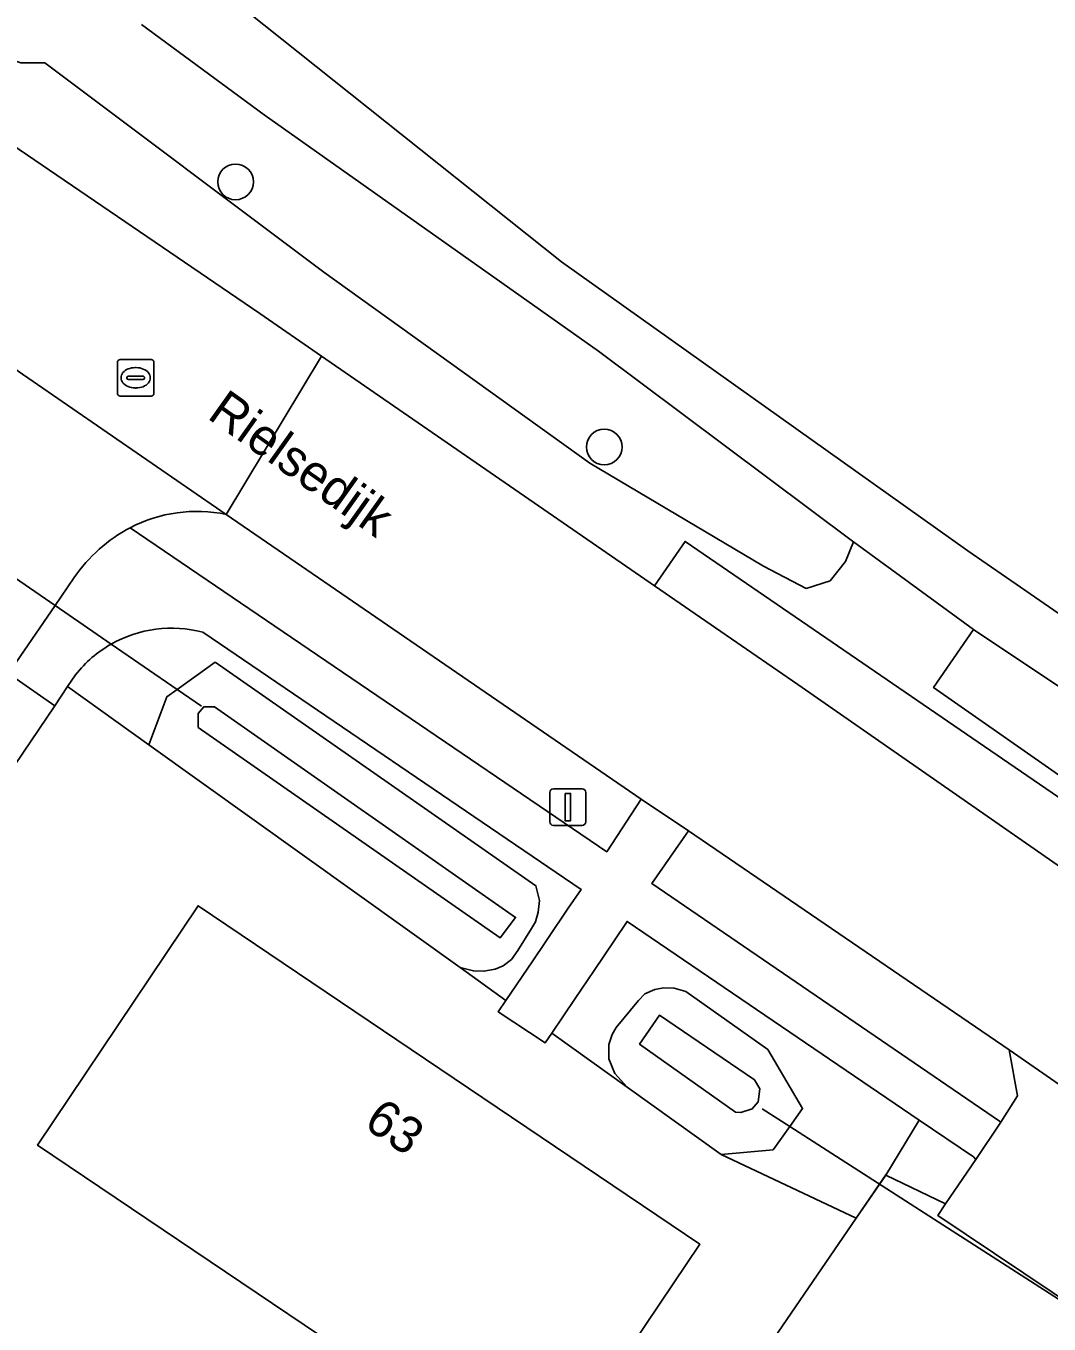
# Model space of a CAD drawing. Extents: x 163859 to 164644, y 379566 to 382155.
# Drawn here: x 164197.07 to 164225.13, y 381831.56 to 381867.17 of the extents above; entities that cross this region are included whole.
import ezdxf

# ---------------------------------------------------------------- set-up
doc = ezdxf.new("R2010")
doc.units = 0
for name, color, linetype in [('IMGEO_Boom', 7, 'Continuous'), ('IMGEO_Duiker', 7, 'Continuous'), ('IMGEO_Erf', 7, 'Continuous'), ('IMGEO_Grasland_agrarisch', 7, 'Continuous'), ('IMGEO_Grasland_overig', 7, 'Continuous'), ('IMGEO_Groenvoorziening', 7, 'Continuous'), ('IMGEO_Lichtmast', 7, 'Continuous'), ('IMGEO_Muur', 7, 'Continuous'), ('IMGEO_Oever', 7, 'Continuous'), ('IMGEO_Openbare_ruimte_label', 7, 'Continuous'), ('IMGEO_Pand', 7, 'Continuous'), ('IMGEO_Pand_nummerreeks', 7, 'Continuous'), ('IMGEO_Parkeervlak_halfverhard', 7, 'Continuous'), ('IMGEO_Rijbaan_lokaal_gesloten', 7, 'Continuous'), ('IMGEO_Rijbaan_lokaal_open', 7, 'Continuous'), ('IMGEO_Rioolput', 7, 'Continuous'), ('IMGEO_Sloot', 7, 'Continuous'), ('IMGEO_Voetpad_halfverhard', 7, 'Continuous'), ('IMGEO_Voetpad_open', 7, 'Continuous'), ('IMGEO_Waterloop', 7, 'Continuous')]:
    doc.layers.add(name, color=color, linetype=linetype)

msp = doc.modelspace()

# ---------------------------------------------------------------- linework, layer by layer
at = {"layer": 'IMGEO_Boom'}
for centre in [(164202.821, 381862.893), (164212.934, 381855.62)]:
    msp.add_circle(centre, 0.489, dxfattribs=at)
at = {"layer": 'IMGEO_Duiker'}
for points in [[(164190.042, 381856.658), (164190.846, 381856.104), (164192.323, 381855.089), (164194.104, 381853.864), (164197.871, 381851.272), (164199.409, 381850.214), (164201.216, 381848.971), (164201.883, 381848.512)], [(164217.268, 381837.469), (164218.022, 381836.985), (164233.632, 381826.955)]]:
    msp.add_lwpolyline(points, dxfattribs=at)
at = {"layer": 'IMGEO_Erf'}
for points in [[(164235.043, 381794.138), (164205.955, 381814.209), (164212.364, 381823.54), (164216.274, 381829.253), (164219.843, 381834.466), (164216.141, 381836.213), (164213.566, 381838.056), (164211.492, 381839.541), (164211.311, 381839.272), (164210.023, 381840.13), (164210.234, 381840.441), (164208.977, 381841.341), (164200.437, 381847.454), (164198.212, 381849.047), (164197.859, 381848.521), (164188.424, 381834.578), (164188.626, 381834.431), (164188.179, 381833.768), (164185.088, 381829.228), (164165.885, 381800.687)], [(164287.783, 381790.232), (164256.006, 381812.389), (164255.882, 381812.656), (164254.893, 381811.01), (164254.142, 381811.525), (164232.273, 381826.526), (164232.842, 381827.338), (164225.998, 381831.919), (164222.08, 381834.543), (164222.298, 381834.862), (164220.66, 381835.65), (164219.843, 381834.466), (164216.274, 381829.253), (164224.066, 381823.939), (164225.891, 381826.571), (164230.279, 381823.603), (164230.417, 381823.852)]]:
    msp.add_lwpolyline(points, dxfattribs=at)
msp.add_lwpolyline([(164197.39, 381836.467), (164201.794, 381843.035), (164208.819, 381838.297), (164215.56, 381833.752), (164211.149, 381827.193)], close=True, dxfattribs=at)
at = {"layer": 'IMGEO_Grasland_agrarisch'}
msp.add_lwpolyline([(164303.655, 381951.333), (164266.944, 381922.737), (164277.667, 381908.3), (164278.876, 381906.816), (164278.809, 381906.762), (164279.852, 381905.358), (164303.691, 381871.549), (164284.619, 381860.24), (164259.755, 381889.448), (164267.387, 381895.767), (164258.029, 381908.469), (164254.791, 381905.941), (164252.396, 381909.265), (164208.654, 381876.058), (164201.663, 381868.745), (164211.763, 381860.7), (164222.906, 381852.769), (164256.457, 381829.627), (164286.005, 381809.753), (164322.428, 381783.408), (164335.006, 381775.051), (164338.747, 381777.229), (164392.726, 381806.597)], dxfattribs=at)
at = {"layer": 'IMGEO_Grasland_overig'}
for points in [[(164286.005, 381809.753), (164256.457, 381829.627), (164222.906, 381852.769), (164211.763, 381860.7), (164201.663, 381868.745)], [(164200.241, 381867.209), (164203.607, 381864.729), (164212.773, 381858.254), (164219.743, 381853.042), (164219.769, 381853.023), (164223.061, 381850.617), (164244.45, 381836.352), (164263.512, 381823.639), (164264.597, 381822.915)], [(164202.265, 381849.716), (164211.061, 381843.586), (164211.155, 381843.184), (164211.125, 381842.859), (164211.052, 381842.593), (164210.941, 381842.409), (164210.564, 381841.812), (164210.386, 381841.558), (164210.157, 381841.388), (164209.943, 381841.299), (164209.632, 381841.24), (164209.344, 381841.247), (164208.977, 381841.341), (164210.234, 381840.441), (164210.971, 381841.528), (164211.31, 381842.028), (164211.367, 381842.112), (164211.947, 381842.968), (164212.298, 381843.486), (164201.922, 381850.538)], [(164198.432, 381849.375), (164198.212, 381849.047), (164200.437, 381847.454), (164200.931, 381848.768), (164201.216, 381848.971), (164202.265, 381849.716)]]:
    msp.add_lwpolyline(points, dxfattribs=at)
for centre, radius, start, end in [((164201.063, 381847.292), 3.358, 75.1807, 119.5125), ((164201.064, 381847.299), 3.352, 119.5802, 141.7285)]:
    msp.add_arc(centre, radius, start, end, dxfattribs=at)
at = {"layer": 'IMGEO_Groenvoorziening'}
for points in [[(164261.825, 381821.183), (164221.968, 381849.023), (164223.061, 381850.617), (164219.769, 381853.023), (164219.553, 381852.482), (164219.129, 381851.953), (164218.468, 381851.741), (164217.304, 381852.35), (164212.541, 381855.181), (164205.239, 381860.42), (164197.592, 381866.161), (164196.931, 381866.161), (164195.529, 381866.611), (164195.052, 381867.457), (164195.268, 381868.391), (164195.29, 381868.489), (164195.394, 381868.583), (164194.945, 381868.909), (164183.031, 381877.576), (164180.902, 381879.968), (164176.8, 381882.795)], [(164175.458, 381878.387), (164203.483, 381859.285), (164205.181, 381858.114), (164214.31, 381851.815), (164215.15, 381853.032), (164227.892, 381844.304), (164227.341, 381843.488), (164229.978, 381841.659), (164230.539, 381842.463), (164236.331, 381838.448), (164235.41, 381837.168), (164242.387, 381832.326), (164242.758, 381832.059), (164272.361, 381810.742), (164289.667, 381798.436), (164312.339, 381782.446)], [(164199.933, 381853.407), (164213.001, 381844.519), (164213.948, 381845.959), (164202.562, 381853.773)]]:
    msp.add_lwpolyline(points, dxfattribs=at)
for points in [[(164215.248, 381845.088), (164214.237, 381843.648), (164223.774, 381837.13), (164223.813, 381837.103), (164224.271, 381837.825), (164224.041, 381839.088)], [(164221.574, 381837.159), (164213.561, 381842.608), (164213.204, 381842.078), (164212.655, 381841.264), (164212.135, 381840.494), (164211.492, 381839.541), (164213.566, 381838.056), (164213.223, 381838.437), (164213.061, 381838.836), (164213.061, 381839.228), (164213.15, 381839.509), (164213.258, 381839.698), (164213.869, 381840.436), (164214.044, 381840.618), (164214.325, 381840.736), (164214.561, 381840.788), (164214.849, 381840.78), (164215.169, 381840.688), (164217.418, 381839.098), (164218.372, 381837.475), (164218.022, 381836.985), (164217.566, 381836.344), (164216.141, 381836.213), (164219.843, 381834.466), (164220.66, 381835.65)], [(164223.128, 381836.076), (164223.059, 381836.149), (164221.574, 381837.159), (164220.66, 381835.65), (164222.298, 381834.862)]]:
    msp.add_lwpolyline(points, close=True, dxfattribs=at)
msp.add_arc((164201.76, 381849.906), 3.949, 78.2887, 117.5624, dxfattribs=at)
at = {"layer": 'IMGEO_Lichtmast'}
for p, q in [((164211.438, 381845.342), (164211.438, 381846.142)), ((164211.438, 381846.142), (164211.438, 381845.342)), ((164211.538, 381846.242), (164212.328, 381846.242)), ((164212.328, 381846.242), (164211.538, 381846.242)), ((164212.428, 381846.142), (164212.428, 381845.342)), ((164212.428, 381845.342), (164212.428, 381846.142)), ((164212.328, 381845.242), (164211.538, 381845.242)), ((164211.538, 381845.242), (164212.328, 381845.242))]:
    msp.add_line(p, q, dxfattribs=at)
msp.add_lwpolyline([(164211.858, 381846.117), (164212.008, 381846.117), (164212.008, 381845.367), (164211.858, 381845.367), (164211.858, 381846.117)], dxfattribs=at)
for centre, start, end in [((164211.538, 381846.142), 90, 180), ((164211.538, 381846.142), 90, 180), ((164212.328, 381846.142), 0, 90), ((164212.328, 381846.142), 360, 90), ((164211.538, 381845.342), 180, 270), ((164211.538, 381845.342), 180, 270), ((164212.328, 381845.342), 270, 0), ((164212.328, 381845.342), 270, 0)]:
    msp.add_arc(centre, 0.1, start, end, dxfattribs=at)
at = {"layer": 'IMGEO_Muur'}
for points in [[(164219.843, 381834.466), (164220.477, 381835.391)], [(164220.477, 381835.391), (164220.655, 381835.651)], [(164216.274, 381829.253), (164219.843, 381834.466)]]:
    msp.add_lwpolyline(points, dxfattribs=at)
at = {"layer": 'IMGEO_Oever'}
for points in [[(164202.265, 381849.716), (164201.216, 381848.971), (164200.931, 381848.768), (164200.437, 381847.454), (164208.977, 381841.341), (164209.344, 381841.247), (164209.632, 381841.24), (164209.943, 381841.299), (164210.157, 381841.388), (164210.386, 381841.558), (164210.564, 381841.812), (164210.941, 381842.409), (164211.052, 381842.593), (164211.125, 381842.859), (164211.155, 381843.184), (164211.061, 381843.586)], [(164201.946, 381848.491), (164202.241, 381848.491), (164210.501, 381842.717), (164210.075, 381842.154), (164201.798, 381847.929), (164201.798, 381848.313)], [(164218.372, 381837.475), (164217.418, 381839.098), (164215.169, 381840.688), (164214.849, 381840.78), (164214.561, 381840.788), (164214.325, 381840.736), (164214.044, 381840.618), (164213.869, 381840.436), (164213.258, 381839.698), (164213.15, 381839.509), (164213.061, 381839.228), (164213.061, 381838.836), (164213.223, 381838.437), (164213.566, 381838.056), (164216.141, 381836.213), (164217.566, 381836.344), (164218.022, 381836.985)], [(164216.993, 381837.465), (164216.683, 381837.362), (164216.535, 381837.376), (164213.901, 381839.242), (164214.453, 381840.037), (164217.052, 381838.263), (164217.2, 381838.012), (164217.156, 381837.657)]]:
    msp.add_lwpolyline(points, close=True, dxfattribs=at)
at = {"layer": 'IMGEO_Pand'}
msp.add_lwpolyline([(164201.794, 381843.035), (164197.39, 381836.467), (164211.149, 381827.193), (164215.56, 381833.752), (164208.819, 381838.297)], close=True, dxfattribs=at)
at = {"layer": 'IMGEO_Parkeervlak_halfverhard'}
msp.add_lwpolyline([(164215.15, 381853.032), (164214.31, 381851.815), (164218.242, 381849.102), (164233.939, 381838.189), (164234.184, 381838.019), (164235.41, 381837.168), (164236.331, 381838.448), (164230.539, 381842.463), (164229.978, 381841.659), (164227.341, 381843.488), (164227.892, 381844.304)], close=True, dxfattribs=at)
at = {"layer": 'IMGEO_Rijbaan_lokaal_gesloten'}
for points in [[(164184.975, 381865.791), (164193.85, 381859.772), (164202.562, 381853.773), (164205.181, 381858.114), (164203.483, 381859.285), (164175.458, 381878.387), (164175.446, 381878.395), (164166.649, 381884.443), (164166.499, 381884.544), (164143.584, 381899.974), (164141.791, 381898.302), (164187.087, 381867.645)], [(164218.242, 381849.102), (164214.31, 381851.815), (164205.181, 381858.114), (164202.562, 381853.773), (164213.948, 381845.959), (164215.248, 381845.088), (164224.041, 381839.088), (164229.404, 381835.36), (164230.42, 381834.663), (164231.119, 381834.18), (164233.939, 381838.189)]]:
    msp.add_lwpolyline(points, close=True, dxfattribs=at)
at = {"layer": 'IMGEO_Rijbaan_lokaal_open'}
for points in [[(164202.562, 381853.773), (164193.85, 381859.772)], [(164183.294, 381829.671), (164187.087, 381835.261), (164196.592, 381849.406), (164197.871, 381851.272), (164198.396, 381852.037)]]:
    msp.add_lwpolyline(points, dxfattribs=at)
msp.add_lwpolyline([(164224.041, 381839.088), (164224.271, 381837.825), (164223.813, 381837.103), (164223.128, 381836.076), (164222.298, 381834.862), (164222.08, 381834.543), (164225.998, 381831.919), (164227.089, 381833.448), (164227.793, 381834.436), (164227.67, 381834.52), (164228.079, 381835.092), (164229.404, 381835.36)], close=True, dxfattribs=at)
for centre, radius, start, end in [((164201.76, 381849.906), 3.949, 78.2887, 117.5624), ((164201.849, 381849.71), 4.164, 117.3979, 146.0263)]:
    msp.add_arc(centre, radius, start, end, dxfattribs=at)
at = {"layer": 'IMGEO_Rioolput'}
for p, q in [((164199.579, 381857.093), (164199.579, 381857.945)), ((164199.654, 381858.019), (164200.506, 381858.019)), ((164200.067, 381857.799), (164200.092, 381857.799)), ((164200.58, 381857.945), (164200.58, 381857.093)), ((164199.838, 381857.513), (164199.838, 381857.525)), ((164200.276, 381857.476), (164199.878, 381857.476)), ((164199.881, 381857.562), (164200.279, 381857.562)), ((164200.322, 381857.525), (164200.322, 381857.513)), ((164200.09, 381857.239), (164200.065, 381857.239)), ((164200.506, 381857.019), (164199.654, 381857.019))]:
    msp.add_line(p, q, dxfattribs=at)
for points in [[(164199.579, 381857.093), (164199.579, 381857.945)], [(164199.654, 381858.019), (164200.506, 381858.019)], [(164200.58, 381857.945), (164200.58, 381857.093)], [(164200.506, 381857.019), (164199.654, 381857.019)]]:
    msp.add_lwpolyline(points, dxfattribs=at)
for centre, radius, start, end in [((164199.656, 381857.943), 0.0765, 91.552, 178.448), ((164199.656, 381857.943), 0.0765, 91.552, 178.448), ((164200.504, 381857.943), 0.0765, 1.552, 88.448), ((164200.504, 381857.943), 0.0765, 1.552, 88.448), ((164199.878, 381857.522), 0.0403, 85.8775, 175.7526), ((164199.875, 381857.512), 0.0366, 178.938, 274.7102), ((164200.279, 381857.519), 0.043, 264.8664, 352.4533), ((164200.283, 381857.524), 0.0386, 1.7309, 96.639), ((164199.656, 381857.095), 0.0765, 181.552, 268.448), ((164199.656, 381857.095), 0.0765, 181.552, 268.448), ((164200.504, 381857.095), 0.0765, 271.552, 358.448), ((164200.504, 381857.095), 0.0765, 271.552, 358.448)]:
    msp.add_arc(centre, radius, start, end, dxfattribs=at)
for centre, major_axis, ratio, start_param, end_param in [((164200.066, 381857.519), (-0.387, 0.002), 0.722429, 4.712389, 7.853982), ((164200.091, 381857.519), (-0.39, 0.002), 0.717154, 1.570796, 4.712389)]:
    msp.add_ellipse(centre, major_axis=major_axis, ratio=ratio, start_param=start_param, end_param=end_param, dxfattribs=at)
at = {"layer": 'IMGEO_Sloot'}
for points in [[(164210.075, 381842.154), (164210.501, 381842.717), (164202.241, 381848.491), (164201.946, 381848.491), (164201.798, 381848.313), (164201.798, 381847.929)], [(164214.453, 381840.037), (164213.901, 381839.242), (164216.535, 381837.376), (164216.683, 381837.362), (164216.993, 381837.465), (164217.156, 381837.657), (164217.2, 381838.012), (164217.052, 381838.263)]]:
    msp.add_lwpolyline(points, close=True, dxfattribs=at)
at = {"layer": 'IMGEO_Voetpad_halfverhard'}
msp.add_lwpolyline([(164197.859, 381848.521), (164196.592, 381849.406), (164187.087, 381835.261), (164187.373, 381834.333), (164188.179, 381833.768), (164188.626, 381834.431), (164188.424, 381834.578)], close=True, dxfattribs=at)
at = {"layer": 'IMGEO_Voetpad_open'}
for points in [[(164214.237, 381843.648), (164215.248, 381845.088), (164213.948, 381845.959), (164213.001, 381844.519), (164199.933, 381853.407)], [(164198.396, 381852.037), (164197.871, 381851.272), (164196.592, 381849.406), (164197.859, 381848.521), (164198.212, 381849.047), (164198.432, 381849.375)], [(164201.922, 381850.538), (164212.298, 381843.486), (164211.947, 381842.968), (164211.367, 381842.112), (164211.31, 381842.028), (164210.971, 381841.528), (164210.234, 381840.441), (164210.023, 381840.13), (164211.311, 381839.272), (164211.492, 381839.541), (164212.135, 381840.494), (164212.655, 381841.264), (164213.204, 381842.078), (164213.561, 381842.608), (164221.574, 381837.159), (164223.059, 381836.149), (164223.128, 381836.076), (164223.813, 381837.103), (164223.774, 381837.13), (164214.237, 381843.648)]]:
    msp.add_lwpolyline(points, dxfattribs=at)
for centre, radius, start, end in [((164201.849, 381849.71), 4.164, 117.3979, 146.0263), ((164201.063, 381847.292), 3.358, 75.1807, 119.5125), ((164201.064, 381847.299), 3.352, 119.5802, 141.7285)]:
    msp.add_arc(centre, radius, start, end, dxfattribs=at)
at = {"layer": 'IMGEO_Waterloop'}
msp.add_lwpolyline([(164195.052, 381867.457), (164195.529, 381866.611), (164196.931, 381866.161), (164197.592, 381866.161), (164205.239, 381860.42), (164212.541, 381855.181), (164217.304, 381852.35), (164218.468, 381851.741), (164219.129, 381851.953), (164219.553, 381852.482), (164219.769, 381853.023), (164219.743, 381853.042), (164212.773, 381858.254), (164203.607, 381864.729), (164200.241, 381867.209)], dxfattribs=at)
msp.add_lwpolyline([(164293.413, 381802.563), (164264.597, 381822.915), (164263.512, 381823.639), (164244.45, 381836.352), (164223.061, 381850.617), (164221.968, 381849.023), (164261.825, 381821.183), (164291.421, 381800.511), (164350.837, 381759.485), (164361.269, 381751.975), (164361.428, 381751.86), (164362.019, 381753.203), (164361.552, 381753.543), (164351.545, 381760.837), (164333.203, 381774.002)], close=True, dxfattribs=at)

# ---------------------------------------------------------------- texts
at = {"layer": 'IMGEO_Openbare_ruimte_label'}
msp.add_text('Rielsedijk', height=1, rotation=324.6089, dxfattribs=at).set_placement((164202.012, 381856.426))
at = {"layer": 'IMGEO_Pand_nummerreeks'}
msp.add_text('63', height=1, rotation=325.995, dxfattribs=at).set_placement((164206.3, 381836.981))

doc.saveas('drawing.dxf')
